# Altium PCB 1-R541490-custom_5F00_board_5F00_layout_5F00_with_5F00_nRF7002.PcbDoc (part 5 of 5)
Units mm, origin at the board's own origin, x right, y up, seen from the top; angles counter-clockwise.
Board outline 180 x 80 mm, 6 copper layers (Top Layer, GND 1, Signal 1, POWER, GND 2, Bottom Layer), stack 1.609 mm thick; 321 components, 275 nets, 828 pads, 1164 vias.
Unrouted connection lines stored in the file: 746.
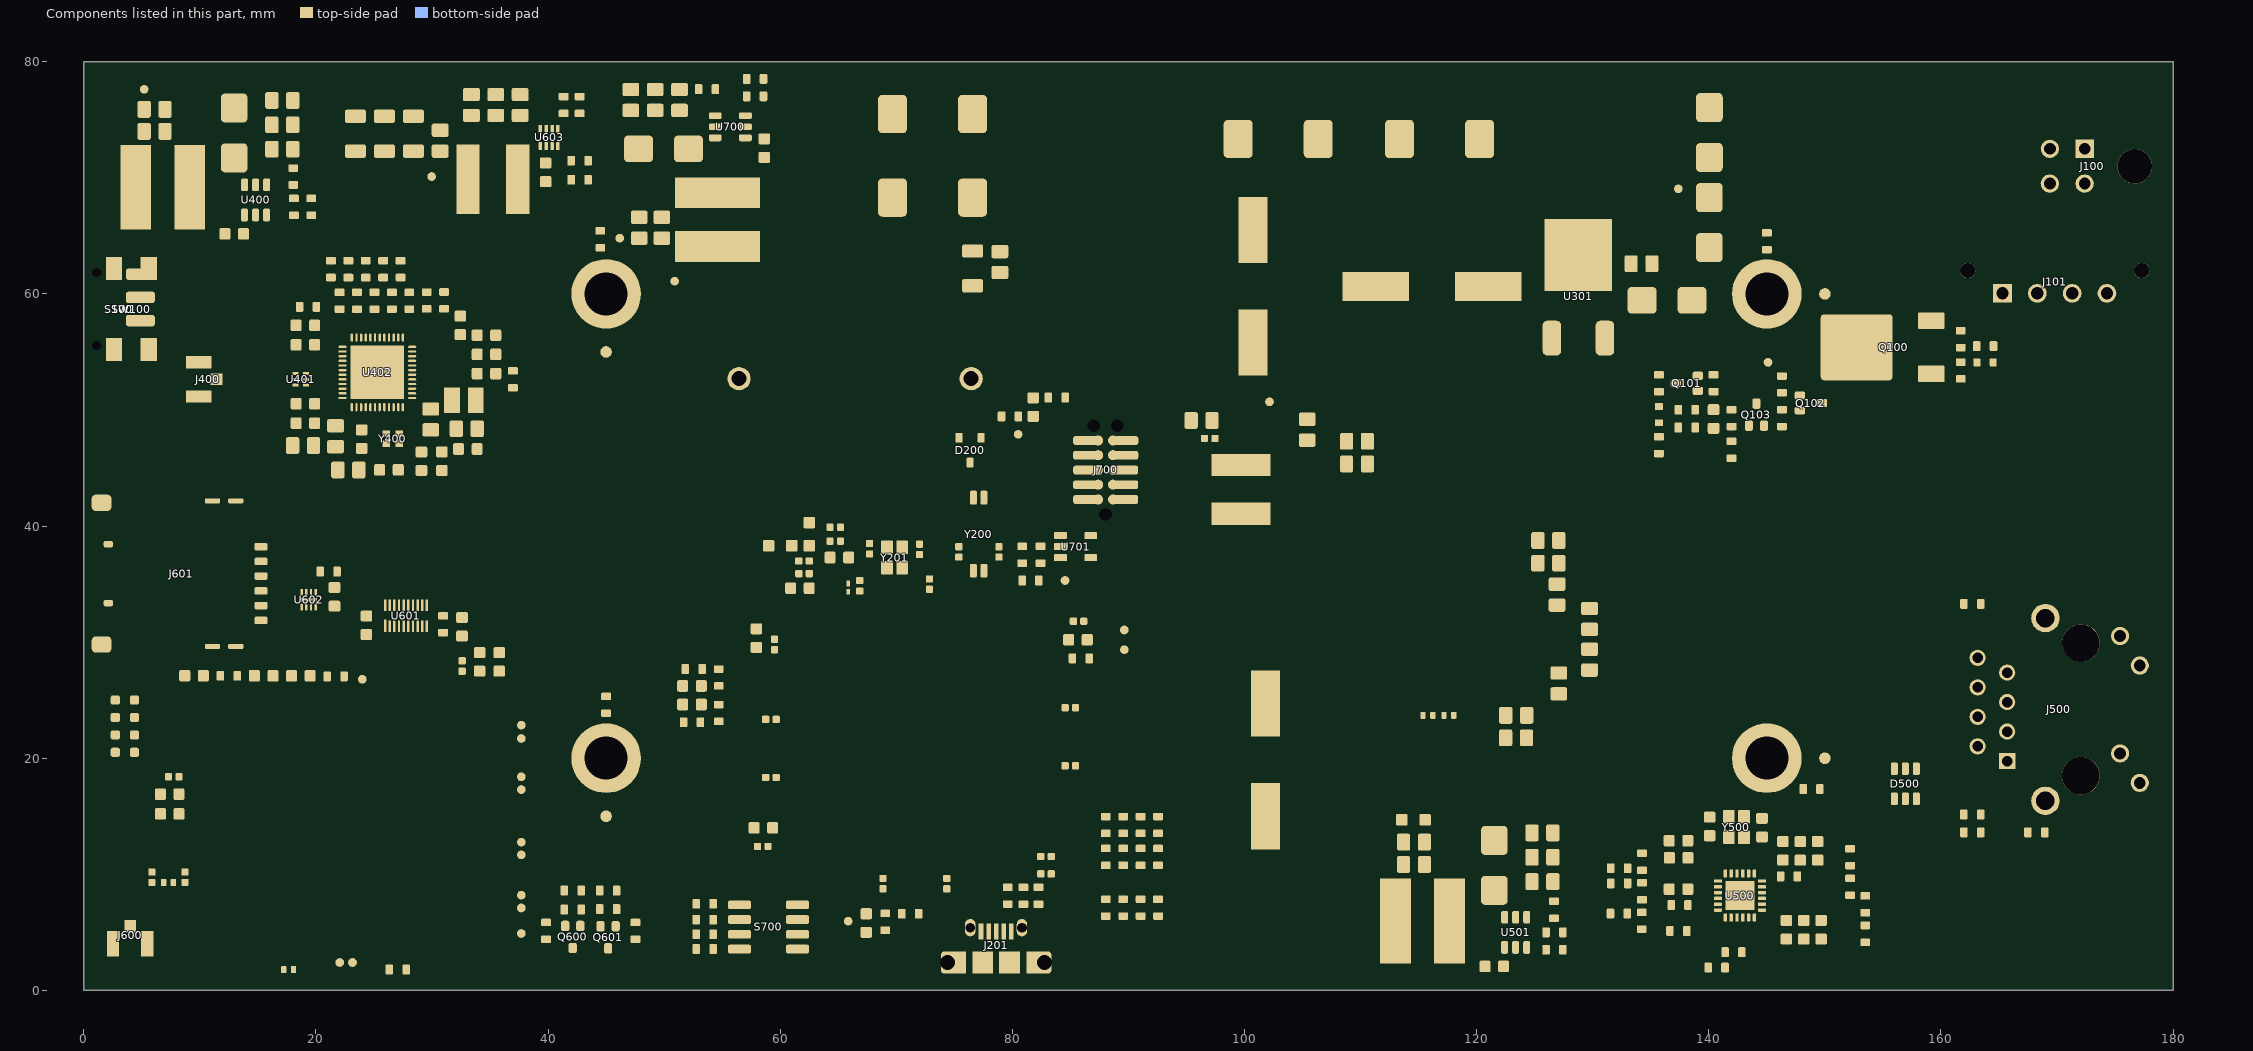
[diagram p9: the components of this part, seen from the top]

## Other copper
Top Layer:
  region net +VCC__: 105.1,71.7 105.1,75 114.6,75 114.6,58.918 119.188,54.33 122.38,54.33 125.75,57.7 127.3,57.7 127.3,54.75 121.15,48.6 104.55,48.6 102.2,46.25 102.2,44.3 97.15,44.3 97.1,44.25 97.1,47.85 96.6,48.35 96.6,52.1 102.2,52.1 108.45,58.35 108.45,61.9
  region net NetQ100_1: 163.413,55.9 163.413,55.112 162.478,54.725 162.112,54.359 161.3,53.8 160.3,52.4 158.2,52.4 158.2,53.8 161.215,55.648 162.112,55.9
  region net NetJ101_1: 166.4,61.1 166.4,58.9 162.5,57.3 162.1,56.9 162.1,56.5 158.338,56.5 158.013,56.825 158.013,58.4 164.531,61.1
  region net NetQ102_1: 148.3,50.9 148.3,51.6 147.5,51.6 147.4,51.7 144.5,51.7 143.8,51 143.8,50.1 144.2,49.7 146.7,49.7 146.7,49.921 147.679,50.9
  region net VBAT: 155.8,52.6 155.8,58.2 148.6,58.2 146.6,56.2 143.356,56.2 141.2,58.356 141.2,62.934 141.2,65.255 140.245,65.255 130.493,75.007 119.2,75.007 119.2,71.7 121.507,71.7 127.856,71.7 136.6,62.956 136.6,54.8 138.8,52.6 148.9,52.6
  region net VCC: 140.896,66.65 142.51,66.65 143.117,67.258 143.117,69.433 142.6,69.95 140.903,69.95 140.496,69.547 140.474,67.077
  region net VCC: 140.897,70.1 142.51,70.1 143.118,70.707 143.118,72.882 142.6,73.4 140.903,73.4 140.496,72.997 140.474,70.526
  region net VIN: 140.897,74.4 142.51,74.4 143.118,75.007 143.118,77.182 142.6,77.7 140.903,77.7 140.496,77.296 140.474,74.826
  region net VBAT: 119.83,75 117.79,75 117.183,74.393 117.183,72.217 117.7,71.7 119.8,71.7
  region net VIN: 69.255,69.946 67.215,69.946 66.607,69.339 66.607,67.164 67.125,66.646 69.225,66.646
  region net VIN: 99.03,75 96.99,75 96.383,74.393 96.383,72.217 96.9,71.7 99,71.7
  pour cut-out: 183.025,33.65 161.275,33.65 161.275,14.75 183.025,14.75
  region net NetC318_2: 134.585,61.93 134.585,63.009 135.5,63.009 135.5,61.93 135.5,54.478 125.096,44.073 120.223,44.073 117.65,41.5 117.55,41.5 113,41.5 113,41.886 112.99,41.896 112.995,41.9 114.1,41.9 119.85,47.65 122.3,47.65 130.25,55.6 130.25,57.45 130.5,57.7 132.35,57.7 133,58.35 133,60.4 134.493,61.842
  region net NetL100_2: 87.291,60.746 91.025,60.746 93.75,63.471 93.75,75.296 89.875,75.296 89.875,69.696 90.498,67.28 90.498,63.084 90.225,62.796 88.925,61.496 88.541,61.496
  region net NetC102_2: 84.375,62.496 83.475,63.396 79.975,63.396 79.675,63.096 75.675,63.096 75.325,66.946 75.325,69.596 75.575,69.946 77.525,69.946 77.825,69.646 84.225,63.846 84.725,63.396 84.725,62.496
  region net NetC104_1: 85.025,62.496 85.025,63.796 84.425,64.396 84.425,65.246 84.394,65.246 79.944,69.696 79.944,71.377 76.025,75.296 76.025,77.146 82.025,77.146 83.775,75.396 83.775,70.046 85.375,68.446 85.375,62.671 85.2,62.496
  region net PVDD: 102.25,42.05 102.25,28.35 103.1,27.5 103.1,21.845 102.25,21.845 100.555,21.845 100.5,21.9 97.15,25.25 97.15,42.05
  region net PVDD: 121.5,26.65 121.55,26.7 123.45,26.7 123.45,25.587 123.1,25.237 123.1,21.05 121.521,21.05 121.521,23.379 121.521,25.657
  region net PVDD: 121.55,33.85 121.55,34.9 123.45,34.9 124.7,36.15 124.7,39.5 125.85,39.5 125.85,35.7 124,33.85
  region net PVDD: 113,42.1 113,42.55 111.952,42.55 110.152,44.35 109.352,45.15 109.352,48 108.2,48 108.2,44.65 108.8,44.65 111.35,42.1 111.95,42.1
  region net NetC614_1: 39.45,73.05 39.2,73.05 38.4,72.85 36.4,72.85 36.4,66.9 38.4,66.9 38.4,70.75 39.2,72.4 39.45,72.4
  region net VCC: 39.7,74.1 40,74.1 40,76.6 38.8,77.8 32.6,77.8 32.15,78.25 31.75,78.25 31.55,78.05 31.55,77.8 31.55,76.6 31.55,76.3 31.7,76.15 32.188,76.15 32.624,76.671 38.2,76.6 39.7,75.1 39.7,74.6
  region net +VCC_modem: 34.1,72.9 34,73 22.5,73 22.5,70.4 28.6,70.4 29.5,69.5 32.1,66.9 34.1,66.9
  region net VCC: 53.833,74.723 54.433,74.723 54.433,74.123 52.611,74.123 52.233,74.502 52.233,76.723 51.933,77.023 46.605,77.023 46.105,76.523 45.733,76.523 45.533,76.723 45.533,78.523 45.733,78.723 46.105,78.723 46.605,78.223 53.333,78.223 53.333,75.223
  region net VDD_MCU: 58.333,65.423 58.333,62.723 47.672,62.723 47.131,63.264 47.131,65.373 51.07,65.373
  region net NetC700_1: 58.333,67.423 58.333,70.023 59.133,70.823 59.133,72.223 58.133,72.223 57.633,72.723 55.318,72.723 54.413,73.628 50.905,73.628 50.905,67.451 50.933,67.423
  region net NetC502_2: 115.1,15.2 115.1,14.2 116,14.2 116.6,13.6 117.2,13.6 117.4,13.8 117.4,15.5 117.2,15.7 116.6,15.7 116.1,15.2
  region net VCC_Ethr: 114.35,2.406 111.65,2.406 111.65,15.172 114.35,15.172
  region net NetC400_1: 7.823,65.467 10.423,65.467 11.223,64.667 12.623,64.667 12.623,65.667 13.123,66.167 13.123,68.482 14.028,69.387 14.028,72.895 7.851,72.895 7.823,72.867
  region net VBAT_nRF: 5.823,65.467 3.123,65.467 3.123,76.669 5.773,76.669 5.773,72.73
  region net VCC: 15.123,69.967 15.123,69.367 14.523,69.367 14.523,71.189 14.902,71.567 17.123,71.567 17.423,71.867 17.423,77.195 16.923,77.695 16.923,78.067 17.123,78.267 18.923,78.267 19.123,78.067 19.123,77.695 18.623,77.195 18.623,70.467 15.623,70.467
  region net VCC: 123.682,6.867 123.682,6.267 123.082,6.267 123.082,8.089 123.461,8.467 125.682,8.467 125.982,8.767 125.982,14.094 125.482,14.594 125.482,14.967 125.682,15.167 127.482,15.167 127.682,14.967 127.682,14.594 127.182,14.094 127.182,7.367 124.182,7.367
  region net NetC511_1: 116.382,2.367 118.982,2.367 119.782,1.567 121.182,1.567 121.182,2.567 121.682,3.067 121.682,5.382 122.587,6.287 122.587,9.794 116.41,9.794 116.382,9.767
  region net VDD_MCU: 59.4,38.8 58.05,39.35 57.748,39.35 57.5,39.102 57.5,37.49 57.75,37.24 58.05,37.24 59.4,37.835
  region net VDD_BUCK: 33.144,51.937 33.144,46.138 34.444,46.138 34.444,49.187 35.294,50.087 35.294,51.637 34.994,51.937 34.444,51.937
  region net GND: 32.894,53.037 32.644,53.287 30.897,53.287 29.856,52.337 28.294,52.337 28.294,51.737 28.961,51.737 29.349,51.487 30.226,51.487 30.842,51.487 30.842,52.187 32.594,52.187 32.594,49.637 31.518,49.187 31.394,49.136 30.565,48.893 29.256,48.893 29.173,48.809 29.173,47.887 29.256,47.737 31.394,47.737 31.844,47.11 31.844,46.138 32.894,46.138 32.894,49.237 32.894,49.637 32.894,52.1
  region net VBAT_nRF: 28.044,51.137 28.544,51.137 29.044,50.637 29.794,50.637 29.794,49.537 29.194,49.537 28.344,49.537 28.044,49.837
  region net VBAT_nRF: 23.094,50.537 23.092,50.539 22.994,50.539 21.094,49.137 21.094,48.262 22.494,48.237 23.194,49.937 23.194,50.537
  region net +VCC_modem: 31.125,23.225 31.157,23.257 32.925,23.257 32.925,26.925 33.025,27.025 36.325,27.025 36.83,26.58 37.575,26.18 37.775,26.18 38.048,26.58 38.048,28.38 37.775,28.78 37.575,28.78 36.83,28.38 36.325,27.969 33.725,27.969 32.925,27.825 32.325,27.825 31.125,24.425
  region net +VCC_modem: 12.455,19.85 12.423,19.818 12.423,18.05 8.755,18.05 8.655,17.95 8.655,14.65 9.1,14.145 9.45,13.493 9.45,13.166 9.1,12.927 7.3,12.927 6.9,13.2 6.9,13.4 7.3,14.145 7.711,14.65 7.711,17.25 7.855,18.05 7.855,18.65 11.255,19.85
Signal 1:
  pour cut-out: 12.8,10.361 12.8,8.141 6.553,8.19 cw(c6.336,10.073) 6.267,8.179 cw(c2.201,13.631) 5.346,7.6 4.6,4.8 3.5,4.8 2.5,6.3 2.716,7.6 3.016,8.784 3.75,9.65 4.816,10.4 7.05,10.468
  pour cut-out: 183.025,33.65 161.275,33.65 161.275,14.75 183.025,14.75
POWER:
  pour cut-out: 18.1,65.162 cw(c18.1,65.818) 17.444,65.818 cw(c18.1,65.818) 18.1,66.474 cw(c18.1,65.818) 18.756,65.818 cw(c18.1,65.818)
  pour cut-out: 128.357,2.842 cw(c128.357,3.498) 127.701,3.498 cw(c128.357,3.498) 128.357,4.155 cw(c128.357,3.498) 129.013,3.498 cw(c128.357,3.498)
  pour cut-out: 43.444,68.25 cw(c43.444,68.906) 42.788,68.906 cw(c43.444,68.906) 43.444,69.562 cw(c43.444,68.906) 44.1,68.906 cw(c43.444,68.906)
  pour cut-out: 12.8,10.361 12.8,8.141 6.553,8.19 cw(c6.336,10.073) 6.267,8.179 cw(c2.201,13.631) 5.346,7.6 4.6,4.8 3.5,4.8 2.5,6.3 2.716,7.6 3.016,8.784 3.75,9.65 4.816,10.4 7.05,10.468
  pour cut-out: 183.025,33.659 161.275,33.659 161.275,14.759 183.025,14.759
GND 1:
  pour cut-out: 12.8,10.361 12.8,8.141 6.553,8.19 cw(c6.336,10.073) 6.267,8.179 cw(c2.201,13.631) 5.346,7.6 4.6,4.8 3.5,4.8 2.5,6.3 2.716,7.6 3.016,8.784 3.75,9.65 4.816,10.4 7.05,10.468
  pour cut-out: 183.025,33.65 161.275,33.65 161.275,14.75 183.025,14.75
GND 2:
  pour cut-out: 183.025,33.65 161.275,33.65 161.275,14.75 183.025,14.75
Bottom Layer:
  region net VBAT: 119,75.1 119,71.7 105.3,58 98.636,58 95.086,54.45 88.7,54.45 88.7,54.974 95.176,61.45 101.85,61.45 115.5,75.1
  pour cut-out: 183.025,33.65 161.275,33.65 161.275,14.75 183.025,14.75

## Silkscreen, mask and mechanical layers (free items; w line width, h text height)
Top Overlay:
  lines w0.15: 151.885,75.78 150.515,77.15 149.887,77.15 148.385,77.157 ; 163.28,62.52 163.28,65.825 ; 166.55,62.52 166.55,65.8 ; 168.242,74.875 170.842,74.875 ; 169.542,73.575 169.542,76.175 ; 169.8,62.52 169.8,65.818 ; 173.15,62.54 173.15,65.793 ; 176.32,62.52 176.32,65.8 ; 148.385,77.157 143.756,77.157 143.756,74.779 148.385,74.8 148.385,77.157 ; 168.242,73.575 170.842,73.575 170.842,76.175 168.242,76.175 168.242,73.575
  lines w0.2: 87.25,57.221 88.129,57.771 ; 88.875,57.221 90.543,57.771 ; 166.55,65.8 176.32,65.8
  text "POWER" at 172.2,77.772 h1.8
  text "-" at 169.336,75.308 h2 r90
  text "+" at 170.653,75.214 h1.5 r90
  text "-" at 169.336,74.008 h2 r90
  text "+" at 170.653,73.914 h1.5 r90
  text "+" at 166.022,63.533 h3 r90
  text "SWITCH" at 7.3,63.329 h1.8 r270
  text "NTC" at 168.495,63.343 h1 r90
  text "GND" at 171.837,63.256 h1 r90
  text "GND" at 175.09,63.186 h1 r90
  text "BATTERY" at 167.675,56.3 h1.8
  text "WIFI" at 8.545,48.782 h1.8
  text "nRST" at 81.2,46.884 h1
  text "GND" at 91.6,46.85 h1
  text "RX" at 81.2,45.584 h1
  text "TX" at 91.6,45.584 h1
  text "SWO" at 81.2,44.334 h1
  text "GND" at 91.6,44.334 h1
  text "GND" at 91.6,43.084 h1
  text "SWCLK" at 81.2,43.034 h1
  text "SWDIO" at 81.2,41.784 h1
  text "3V3" at 91.6,41.784 h1
  text "1" at 0.75,25.35 h1.8 r270
  text "2" at 0.65,23.983 h1.8 r270
  text "3" at 0.672,22.481 h1.8 r270
  text "4" at 0.65,20.982 h1.8 r270
  text "LTE" at 2.45,0.85 h1.8
Board:
  the board outline again, w0.2
Fab Notes:
  rectangle: 53.11,71.46 58.78,76.79
  rectangle: 12.68,65.16 17.95,70.61
  rectangle: 38.48,71.68 42.73,75.09
  rectangle: 22.26,50.25 28.67,56.6
  rectangle: 82.33,56.13 92.24,65.98
  rectangle: 61.81,10.97 82.44,32.83
  rectangle: 10.75,3.84 36.11,25.14
  lines w0.6: 95.8,15.35 98.38,12.77 107.35,12.77 116.47,21.89 141.37,21.89 154.15,34.67 177.13,34.67 179.72,37.26 179.72,79.01 179.17,79.56 97.16,79.56 95.8,78.2 95.8,15.35
  lines w1: -94.17,58.31 5.55,58.31 15.18,67.94 ; -34.89,91.19 15.6,91.19 25.86,80.93 25.86,56.63 ; 3.06,110.54 66.53,110.54 ; 25.02,-10.82 25.02,10.34 25.44,10.76 ; 40.94,72.97 42.407,74.437 42.407,110.54 ; 56.02,74.02 56.02,89.02 62.88,95.88 122.56,95.88 ; 70.22,84.36 141.11,84.36 ; 74.26,20 74.26,-9.28 85.93,-20.95 131.41,-20.95 ; 86.264,63.356 86.264,84.36 ; 184.41,54.17 188.17,50.41 ; 184.64,54.17 184.75,54.17 188.51,57.93 ; 184.79,53.82 246.64,54.05
  text "DC/DC for LTE" at 5.82,113.02 h5
  text "DC/DC for MCU" at 59.28,99.3 h5
  text "nRF7002" at -34.21,92.52 h5
  text "Battery Charger" at 70.46,87.416 h5
  text "DC/DC for nRF7002" at -93.63,60.45 h5
  text "Power zone" at 197.15,56.65 h5
  text "LTE Module" at -0.67,-17.72 h5
  text "MCU STM32" at 88.12,-19 h5
Assembly Top:
  text "J400" at 8.452,52.268 h1
  text "J600" at 2.492,3.668 h1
